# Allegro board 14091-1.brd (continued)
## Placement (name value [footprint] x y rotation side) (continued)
C1744  SC10U6D3V3MX-DL-GP  [C603H36]  124.37 204.22 0 top
C1745  SC2D2U10V3KX-1DLGP-U  [C603H36]  124.24 223.9 180 top
C1753  SCD1U16V2KX-3DLGP  [C402H22]  175.67 105.66 180 top
C1756  SC1KP50V2KX-1DLGP  [C402H22]  164.5 118.36 0 top
C1757  SCD1U16V2KX-3DLGP  [C402H22]  160.43 116.71 90 top
C1760  SCD1U16V2KX-3DLGP  [C402H22]  30.13 23.24 270 bottom
C1764  SCD01U50V2KX-1DLGP  [C402H22]  122.33 12.32 270 bottom
C1769  SCD1U16V2KX-3DLGP  [C402H22]  120.56 7.87 0 bottom
C1770  SC10U10V5KX-2DLGP  [C805H50]  160.18 192.02 270 top
C1771  SC10U10V5KX-2DLGP  [C805H50]  160.18 194.06 270 top
C1773  SC10P50V2JN-4DLGP  [C402H22]  30.77 11.18 270 top
C1774  SC10P50V2JN-4DLGP  [C402H22]  32.67 11.18 90 top
C1780  SC100P50V2JN-3DLGP  [C402H22]  156.5 80.39 90 bottom
C1796  SC1U16V3KX-2DLGP  [C603H36]  80.17 214 90 bottom
C1797  SC1U16V3KX-2DLGP  [C603H36]  80.17 210.57 90 bottom
C1798  SC1U10V2KX-1DLGP  [C402H22]  32.16 7.57 90 bottom
C1799  SC18P50V2JN-1DLGP  [C402H22]  39.15 9.4 90 top
C1800  SC18P50V2JN-1DLGP  [C402H22]  35.72 10.29 270 top
C1801  SC1U25V3KX-1-DLGP  [C603H36]  36.14 13.41 270 bottom
C1802  SC2D2U10V3KX-1DLGP-U  [C603H36]  73.69 29.34 0 top
C1803  SC4D7U6D3V3KX-DLGP  [C603H36]  46.26 15.88 270 top
C1804  SC4D7U6D3V3KX-DLGP  [C603H36]  46.26 14.61 270 top
C1805  SCD1U16V2KX-3DLGP  [C402H22]  30.51 16.38 270 top
C1806  SCD1U16V2KX-3DLGP  [C402H22]  74.71 29.72 0 top
C1807  SCD1U25V3KX-DLGP  [C603H36]  33.31 12.95 180 top
C1808  SCD1U16V2KX-3DLGP  [C402H22]  30.51 15.37 270 top
C1829  SC1U10V2KX-1DLGP  [C402H22]  127.92 4.57 270 top
C1830  SC1U10V2KX-1DLGP  [C402H22]  128.3 9.91 270 top
C1831  SC1U6D3V2KX-DLGP  [C402H22]  128.68 11.3 270 bottom
C1832  SCD1U16V2KX-3DLGP  [C402H22]  126.02 4.57 90 top
C1833  SC10U10V5KX-2DLGP  [C805H50]  122.97 6.86 180 top
C1834  SCD1U16V2KX-3DLGP  [C402H22]  123.1 10.92 270 top
C1835  SC10U10V5KX-2DLGP  [C805H50]  123.73 12.83 270 top
C1836  SC1KP50V2KX-1DLGP  [C402H22]  123.1 10.03 270 top
C1837  SC1KP50V2KX-1DLGP  [C402H22]  123.1 9.14 270 top
C1838  SCD22U10V2KX-2-GP  [C402H22]  88.3 115.32 270 bottom
C1839  SCD22U10V2KX-2-GP  [C402H22]  87.41 112.52 270 bottom
C1840  SCD22U10V2KX-2-GP  [C402H22]  88.3 116.2 270 bottom
C1841  SCD22U10V2KX-2-GP  [C402H22]  92.62 115.7 180 bottom
C1842  SCD22U10V2KX-2-GP  [C402H22]  87.41 113.41 270 bottom
C1843  SCD22U10V2KX-2-GP  [C402H22]  85 113.03 180 bottom
C1844  SCD22U10V2KX-2-GP  [C402H22]  93.51 115.7 180 bottom
C1845  SCD22U10V2KX-2-GP  [C402H22]  84.11 113.03 180 bottom
C1846  SCD1U10V2KX-5DLGP  [C402H22]  92.69 97.97 180 bottom
C1847  SCD082U16V2KX-1-GP  [C402H22]  97.19 96.77 0 top
C1848  SCD68U16V3KX-3-GP  [C603H38]  97.32 99.19 0 top
C1849  SCD082U16V2KX-1-GP  [C402H22]  97.19 94.87 180 top
C1850  SCD082U16V2KX-1-GP  [C402H22]  97.19 92.96 0 top
C1851  SCD1U16V2KX-3DLGP  [C402H22]  48.67 105.79 270 top
C1852  SCD1U16V2KX-3DLGP  [C402H22]  48.67 104.9 270 top
C1853  SCD1U16V2KX-3DLGP  [C402H22]  49.41 88.7 180 top
C1854  SCD1U16V2KX-3DLGP  [C402H22]  47.02 114.05 180 top
C1855  SCD01U50V2KX-1DLGP  [C402H22]  46.77 112.27 90 top
C1856  SCD1U16V2KX-3DLGP  [C402H22]  48.67 103.12 270 top
C1857  SCD1U16V2KX-3DLGP  [C402H22]  48.42 113.67 90 bottom
C1858  SC10U6D3V3MX-DL-GP  [C603H36]  48.17 82.68 90 bottom
C1859  SCD1U16V2KX-3DLGP  [C402H22]  48.42 89.66 90 bottom
C1860  SCD1U16V2KX-3DLGP  [C402H22]  47.4 95.76 90 bottom
C1861  SCD1U16V2KX-3DLGP  [C402H22]  47.79 96.65 270 top
C1864  SCD01U50V2KX-1DLGP  [C402H22]  163.23 91.19 0 top
C1867  SC1U10V2KX-1DLGP  [C402H22]  47.28 91.19 180 bottom
C1868  SCD1U16V2KX-3DLGP  [C402H22]  46.39 91.19 180 bottom
C1869  SCD1U16V2KX-3DLGP  [C402H22]  48.44 94.76 90 bottom
C1925  SC10U10V5KX-2DLGP  [C805H50]  148.37 12.7 90 bottom
C1926  SCD1U16V2KX-3DLGP  [C402H22]  151.42 7.24 270 bottom
C1927  SC10U10V5KX-2DLGP  [C805H50]  150.66 5.08 270 bottom
C1928  SC1KP50V2KX-1DLGP  [C402H22]  151.42 9.02 270 bottom
C1929  SC1KP50V2KX-1DLGP  [C402H22]  151.42 8.13 270 bottom
C2101  SC1U10V2KX-1DLGP  [C402H22]  52.87 139.83 0 top
C2102  SC1U10V2KX-1DLGP  [C402H22]  83.09 157.61 0 bottom
C2103  SC1U10V2KX-1DLGP  [C402H22]  88.43 141.53 270 top
C2104  SC1U10V2KX-1DLGP  [C402H22]  77.5 141.48 90 top
C2105  SC1U10V2KX-1DLGP  [C402H22]  69.88 138.68 270 top
C2106  SC1U10V2KX-1DLGP  [C402H22]  79.54 132.97 90 top
C2107  SC1U10V2KX-1DLGP  [C402H22]  81.06 137.29 180 top
C2108  SC1U10V2KX-1DLGP  [C402H22]  83.35 138.68 270 top
C2109  SC1U10V2KX-1DLGP  [C402H22]  99.35 128.73 0 top
C2110  SCD1U16V2KX-3DLGP  [C402H22]  98.48 128.73 0 top
C2111  SC1U10V2KX-1DLGP  [C402H22]  86.52 157.23 90 bottom
C2112  SCD1U16V2KX-3DLGP  [C402H22]  98.84 147.47 0 top
C2113  SC47U6D3V5MX-1DL-GP  [C805H54]  42.07 138.68 0 top
C2114  SC47U6D3V5MX-1DL-GP  [C805H54]  46.26 138.68 0 top
C2115  SC47U6D3V5MX-1DL-GP  [C805H54]  44.23 138.68 0 top
C2116  SC1U10V2KX-1DLGP  [C402H22]  68.23 148.21 180 top
C2117  SC1U10V2KX-1DLGP  [C402H22]  102.52 148.84 270 top
C2118  SCD1U16V2KX-3DLGP  [C402H22]  102.52 147.96 270 top
C2119  SCD1U16V2KX-3DLGP  [C402H22]  102.52 147.07 270 top
C2120  SC1U10V2KX-1DLGP  [C402H22]  100.87 150.5 0 top
C2121  SCD1U16V2KX-3DLGP  [C402H22]  101.76 150.5 180 top
C3131  SC100P3KV8JN-4-GP  [C1808H87]  65.18 18.16 0 bottom
C3366  SCD1U16V2KX-3DLGP  [C402H22]  141.51 39.93 180 bottom
C3367  SC10U10V5KX-2DLGP  [C805H50]  133.64 33.15 90 bottom
C3452  SCD01U50V2KX-1DLGP  [C402H22]  49.82 17.78 180 top
C3453  SCD1U16V2KX-3DLGP  [C402H22]  38.9 12.57 0 bottom
C3454  SCD1U16V2KX-3DLGP  [C402H22]  35.85 17.53 180 bottom
C3455  SCD1U25V2KX-1-DL-GP  [C402H22]  37.29 20.45 180 bottom
C3456  SCD1U25V2KX-1-DL-GP  [C402H22]  38.01 24.77 180 top
C3457  SCD01U50V2KX-1DLGP  [C402H22]  39.4 25.27 270 top
C3458  SCD01U50V2KX-1DLGP  [C402H22]  39.4 27.3 270 top
C3459  SC10U25V5KX-DL-GP  [C805H58]  45.32 33.43 90 top
C3460  SC10U25V5KX-DL-GP  [C805H58]  45.37 35.69 90 top
C4101  SC1U10V2KX-1DLGP  [C402H22]  103.18 59.56 180 top
C4254  SC10U6D3V3MX-DL-GP  [C603H36]  42.96 109.47 270 bottom
C6701  SCD1U16V2KX-3DLGP  [C402H22]  88.91 64.52 180 top
C6702  SCD1U16V2KX-3DLGP  [C402H22]  88.91 66.45 0 top
C6703  SC10U6D3V3MX-DL-GP  [C603H36]  82.58 65.68 270 top
C6710  SC10U6D3V3MX-DL-GP  [C603H36]  48.42 118.24 270 top
C6711  SCD1U16V2KX-3DLGP  [C402H22]  48.67 104.01 270 top
C6716  SC10U6D3V3MX-DL-GP  [C603H36]  42.96 110.74 270 bottom
C6717  SCD1U16V2KX-3DLGP  [C402H22]  42.96 108.33 90 bottom
C6718  SCD1U16V2KX-3DLGP  [C402H22]  49.44 121.16 180 top
C6724  SCD01U25V2KX-3DLGP  [C402H22]  101 66.93 0 bottom
C6725  SCD1U10V2KX-4GP  [C402H20]  93.89 65.91 270 bottom
C9504  SCD1U16V2KX-3DLGP  [C402H22]  64.55 75.95 180 bottom
C9516  SC4D7U6D3V3KX-DLGP  [C603H36]  58.58 69.22 270 bottom
C9518  SCD1U16V2KX-3DLGP  [C402H22]  56.04 75.82 0 bottom
C9520  SC18P50V2JN-1DLGP  [C402H22]  69.78 52.07 180 top
C9522  SC18P50V2JN-1DLGP  [C402H22]  69.78 50.14 0 top
C9901  SCD1U16V2KX-3DLGP  [C402H22]  19.85 224.66 180 top
C9902  SCD1U16V2KX-3DLGP  [C402H22]  21.24 224.92 0 bottom
C9903  SCD1U16V2KX-3DLGP  [C402H22]  45.37 224.03 180 top
C9904  SCD1U16V2KX-3DLGP  [C402H22]  25.43 224.41 0 bottom
C9905  SCD1U16V2KX-3DLGP  [C402H22]  30.94 224.18 180 top
C11358  SC1U10V2KX-1DLGP  [C402H22]  154.72 64.64 0 top
C11359  SCD1U16V2KX-3DLGP  [C402H22]  153.83 64.64 0 top
C12126  SC47P50V3JN-DLGP  [C603H35]  129.45 56.64 0 bottom
C12131  SC10U10V5KX-2DLGP  [C805H50]  176.82 136.91 180 bottom
C12151  SC2D2U6D3V2MX-DL-GP  [C402H22]  126.04 63.8 180 top
C12152  SC1U10V2KX-1DLGP  [C402H22]  129.45 58.93 180 bottom
C12155  SCD1U16V2KX-3DLGP  [C402H22]  175.42 135.51 180 bottom
C12156  SC1U10V2KX-1DLGP  [C402H22]  170.34 149.99 180 bottom
C12157  SC4D7U6D3V3KX-DLGP  [C603H36]  170.34 136.75 90 bottom
C12158  SCD1U16V2KX-3DLGP  [C402H22]  170.72 137.79 270 bottom
C12159  SC1U10V2KX-1DLGP  [C402H22]  169.58 142.88 270 bottom
C12160  SCD1U16V2KX-3DLGP  [C402H22]  176.94 139.95 90 bottom
C12161  SC1U10V2KX-1DLGP  [C402H22]  174.79 138.94 90 bottom
C12162  SCD1U16V2KX-3DLGP  [C402H22]  173.9 149.73 270 bottom
C12163  SC4D7U6D3V3KX-DLGP  [C603H36]  173.9 150.88 90 bottom
C12169  SC4D7U6D3V3KX-DLGP  [C603H36]  53.5 59.44 270 bottom
C12170  SCD1U16V2KX-3DLGP  [C402H22]  79.66 56.77 90 top
C12171  SCD1U50V3KX-DL-GP  [C603H35]  65.18 64.64 270 bottom
C12172  SCD1U16V2KX-3DLGP  [C402H22]  56.68 66.42 0 bottom
C12174  SC10U10V5KX-2DLGP  [C805H50]  67.47 54.74 270 bottom
C12175  SCD1U16V2KX-3DLGP  [C402H22]  75.6 51.05 270 top
C12176  SCD1U16V2KX-3DLGP  [C402H22]  75.6 50.16 270 top
C12179  SCD1U16V2KX-3DLGP  [C402H22]  72.8 60.58 270 top
C12180  SCD1U16V2KX-3DLGP  [C402H22]  72.8 61.47 270 top
C12181  SCD1U16V2KX-3DLGP  [C402H22]  72.8 62.36 270 top
C12182  SCD1U16V2KX-3DLGP  [C402H22]  72.8 63.25 270 top
C12183  SCD1U16V2KX-3DLGP  [C402H22]  62.39 51.56 90 top
C12184  SCD1U16V2KX-3DLGP  [C402H22]  56.42 51.82 270 top
C12185  SC10U6D3V3MX-DL-GP  [C603H36]  73.19 55.37 90 top
C12186  SCD1U16V2KX-3DLGP  [C402H22]  68.49 57.53 180 bottom
C12187  SCD1U16V2KX-3DLGP  [C402H22]  72.55 54.36 90 top
C12188  SCD1U16V2KX-3DLGP  [C402H22]  67.85 64.14 90 bottom
C12189  SC4D7U6D3V3KX-DLGP  [C603H36]  72.8 55.5 270 bottom
C12190  SC1U25V3KX-1-DLGP  [C603H36]  73.57 75.82 90 top
C12191  SCD1U16V2KX-3DLGP  [C402H22]  65.44 75.95 180 bottom
C12192  SC1U10V2KX-1DLGP  [C402H22]  71.79 77.6 90 top
C12193  SC1U10V2KX-1DLGP  [C402H22]  71.79 78.49 90 top
C12194  SCD1U16V2KX-3DLGP  [C402H22]  56.93 75.82 0 bottom
C12195  SCD1U16V2KX-3DLGP  [C402H22]  57.82 75.82 0 bottom
C12196  SCD1U16V2KX-3DLGP  [C402H22]  55.66 71.12 270 bottom
C12197  SCD1U16V2KX-3DLGP  [C402H22]  54.14 64.39 180 bottom
C12199  SCD1U16V2KX-3DLGP  [C402H22]  119.41 32.64 0 bottom
C12200  SCD1U16V2KX-3DLGP  [C402H22]  137.07 39.62 90 top
C12201  SCD01U50V2KX-1DLGP  [C402H22]  135.42 30.99 270 bottom
C12202  SCD1U16V2KX-3DLGP  [C402H22]  136.81 31.65 0 top
C12203  SCD01U50V2KX-1DLGP  [C402H22]  130.21 40.51 270 top
C12204  SCD1U16V2KX-3DLGP  [C402H22]  129.32 31.6 270 top
C12205  SCD01U50V2KX-1DLGP  [C402H22]  130.21 39.62 270 top
C12206  SCD1U16V2KX-3DLGP  [C402H22]  135.03 41.15 180 top
C12207  SCD01U50V2KX-1DLGP  [C402H22]  135.92 41.15 180 top
C12208  SCD1U16V2KX-3DLGP  [C402H22]  139.35 36.2 270 top
C12209  SCD1U16V2KX-3DLGP  [C402H22]  139.35 37.08 270 top
C12210  SCD1U16V2KX-3DLGP  [C402H22]  139.35 34.42 270 top
C12211  SCD1U16V2KX-3DLGP  [C402H22]  139.35 35.31 270 top
C12212  SCD1U16V2KX-3DLGP  [C402H22]  139.35 32.38 270 top
C12213  SCD1U16V2KX-3DLGP  [C402H22]  139.35 33.27 270 top
C12214  SCD1U16V2KX-3DLGP  [C402H22]  139.35 37.97 270 top
C12215  SCD1U16V2KX-3DLGP  [C402H22]  139.35 38.86 270 top
C12216  SCD1U16V2ZY-2DLGP  [C402H22]  120.05 23.62 90 top
C12217  SCD1U16V2ZY-2DLGP  [C402H22]  127.19 20.07 90 top
C12218  SC33P50V2JN-3DLGP  [C402H22]  124.62 20.19 180 bottom
C12219  SC33P50V2JN-3DLGP  [C402H22]  124.24 19.05 270 top
C12244  SC10U6D3V3MX-DL-GP  [C603H36]  54.9 75.56 0 bottom
C12245  SC10U10V5KX-2DLGP  [C805H50]  56.8 63.63 180 bottom
C12246  SC10U10V5KX-2DLGP  [C805H50]  56.8 59.94 180 bottom
C12249  SCD1U16V2KX-3DLGP  [C402H22]  141.89 64.52 180 bottom
C12250  SCD1U16V2KX-3DLGP  [C402H22]  118.14 48.01 0 top
C12251  SC1U10V2KX-1DLGP  [C402H22]  148.24 47.75 270 top
C12261  SC1U10V2KX-1DLGP  [C402H22]  39.12 128.27 270 top
C12262  SCD68U16V3KX-4-GP  [C603H36]  153.96 41.4 270 top
C12263  SCD027U50V3KX-DL-GP  [C603H36]  166.43 56.69 0 top
C12264  SCD68U16V3KX-4-GP  [C603H36]  160.43 41.4 270 top
C12265  SCD01U50V3KX-4DLGP  [C603H36]  158.66 37.08 180 bottom
C12266  SC1U25V3KX-1-DLGP  [C603H36]  160.69 56.52 0 top
C12331  SC1U10V2KX-1DLGP  [C402H22]  161.07 58.29 90 top
C12332  SC1U10V2KX-1DLGP  [C402H22]  157.64 58.29 270 top
C12333  SC1KP50V2KX-1DLGP  [C402H22]  165.39 51.69 180 top
C12334  SC1000P50V3JN-DLGP  [C603H36]  159.42 35.31 270 top
C12335  SCD1U25V2KX-1-DL-GP  [C402H22]  151.16 119.38 180 top
C12336  SCD22U10V2KX-2-GP  [C402H22]  60.99 150.5 180 top
C12337  SCD22U10V2KX-2-GP  [C402H22]  63.03 143 90 top
C12338  SCD1U16V2KX-3DLGP  [C402H22]  62.39 150.5 180 top
C12339  SCD1U16V2KX-3DLGP  [C402H22]  63.28 150.5 180 top
C12340  SCD22U10V2KX-2-GP  [C402H22]  63.03 148.21 90 top
C12341  SCD22U10V2KX-2-GP  [C402H22]  63.03 145.41 90 top
C12342  SCD1U16V2KX-3DLGP  [C402H22]  69.12 156.46 270 bottom
C12343  SCD1U16V2KX-3DLGP  [C402H22]  69.12 155.57 270 bottom
C12344  SCD22U10V2KX-2-GP  [C402H22]  63.03 147.32 90 top
C12345  SCD22U10V2KX-2-GP  [C402H22]  63.03 146.3 90 top
C12346  SCD1U16V2KX-3DLGP  [C402H22]  67.98 157.61 90 top
C12347  SCD1U16V2KX-3DLGP  [C402H22]  67.98 158.5 90 top
C12348  SCD22U10V2KX-2-GP  [C402H22]  60.1 150.5 180 top
C12349  SCD22U10V2KX-2-GP  [C402H22]  63.03 143.89 90 top
C12350  SC220P50V2KX-3DLGP  [C402H22]  106.36 126.87 270 bottom
C12351  SCD1U16V2KX-3DLGP  [C402H22]  66.45 192.15 270 top
C12352  SC10U6D3V2MX-2-GP  [C402-TO0D2H28]  56.29 140.34 90 top
C12353  SC1U10V2KX-1DLGP  [C402H22]  107.6 151.26 270 bottom
C12354  SC1U10V2KX-1DLGP  [C402H22]  107.6 152.15 270 bottom
C12355  SC12P50V2JN-DL-GP  [C402H22]  64.42 159.38 0 top
C12356  SC12P50V2JN-DL-GP  [C402H22]  64.93 156.77 90 top
C12357  SC3D3P50V2CN-DL-GP  [C402H22]  90.58 132.97 180 top
C12358  SC3D3P50V2CN-DL-GP  [C402H22]  90.58 131.06 0 top
C12361  SC10U10V5KX-2DLGP  [C805H50]  90.2 7.37 270 top
C12362  SCD1U16V2KX-3DLGP  [C402H22]  90.84 18.8 270 top
C12363  SC1KP50V2KX-1DLGP  [C402H22]  90.33 21.34 180 top
C12364  SC10U10V5KX-2DLGP  [C805H50]  90.2 9.4 270 top
C12365  SCD1U16V2KX-3DLGP  [C402H22]  157.26 102.23 0 bottom
C12368  SCD01U50V2KX-1DLGP  [C402H22]  121.7 71.37 180 top
C12369  SCD1U16V2KX-3DLGP  [C402H22]  114.46 58.55 180 top
C12370  SCD1U16V2KX-3DLGP  [C402H22]  127.92 30.1 180 top
C12371  SCD1U16V2KX-3DLGP  [C402H22]  72.8 64.14 270 top
C12372  SCD1U16V2KX-3DLGP  [C402H22]  72.8 66.67 270 top
C12373  SCD1U16V2KX-3DLGP  [C402H22]  72.8 65.02 270 top
C12374  SCD1U16V2KX-3DLGP  [C402H22]  72.8 67.56 270 top
C12375  SCD1U16V2KX-3DLGP  [C402H22]  160.18 59.69 0 top
C12376  SC6D8P50V2CN-DL-GP  [C402H22]  169.07 141.48 0 bottom
C12377  SC100P50V2JN-3DLGP  [C402H22]  73.82 138.81 90 top
C12378  SC33P50V2JN-3DLGP  [C402H22]  168.69 152.02 180 bottom
C12379  SC33P50V2JN-3DLGP  [C402H22]  168.69 153.92 0 bottom
C12380  SC33P50V2JN-3DLGP  [C402H22]  169.58 146.81 270 bottom
C12381  SC33P50V2JN-3DLGP  [C402H22]  169.58 145.92 270 bottom
C12382  SCD1U16V2KX-3DLGP  [C402H22]  47.79 175.13 135 bottom
C12383  SCD1U16V2KX-3DLGP  [C402H22]  79.41 199.26 315 bottom
C12384  SC1U10V2KX-1DLGP  [C402H22]  92.11 51.05 90 top
C12385  SCD1U16V2KX-3DLGP  [C402H22]  145.45 45.72 270 top
C12386  SCD1U16V2KX-3DLGP  [C402H22]  83.22 31.62 180 top
CN3  ACES-CON4-37-GP  [88459-047N]  85.76 125.09 225 bottom
CONVT1  CLX-CON10-10-GP  [CI1410M1HRL-NH]  25 36.65 270 top
CPU1  SKYLAKE-GP  [BGA1356M4224H54]  83 165 270 top
D1  1SS355-4-GP  [SOD323AKH38]  13.88 220.47 180 top
D2  BAS40C-2-GP  [SOT-23-9H44]  144.94 81.41 180 top
D3  RB551V30-GP  [SOD323AKH38]  140.9 81.28 270 top
D4  TVLST2304BD0-GP  [SOT-6H58]  172.37 105.92 270 top
D7  BAT54A-12-GP  [SOT23-2D4-312H44]  85.76 82.93 270 top
D16  P6SMB27A-1-GP  [DO214AAAK-1121H97]  60.36 22.86 180 top
D19  BAV99GP-GP  [SOT23-2D4-312H48]  58.83 36.2 0 bottom
D21  AZ2015-01H-GP  [SOD523AKH28]  162.47 87.63 90 top
D24  TVLST2304BD0-GP  [SOT-6H58]  106.46 32.26 180 top
D32  BX310F-R1-00000-GP  [D4724AKH44]  33.94 34.42 0 bottom
D34  BAT54A-12-GP  [SOT23-2D4-312H44]  104.81 110.36 90 top
D5201  BAT54C-12-GP  [SOT-23-9H44]  120.05 26.16 0 top
D5202  BZX84-C6V8-GP  [SOT-23-9H44]  114.97 26.16 180 top
D5203  SP3010-04UTG-GP  [SLP2510P8-1H22]  106.59 21.59 0 top
D5204  SP3010-04UTG-GP  [SLP2510P8-1H22]  106.71 11.81 180 top
D5205  1SS355-4-GP  [SOD323AKH38]  125.13 30.1 90 top
D5206  1SS355GP-GP  [SOD323AKH40]  167.67 88.65 180 bottom
D5207  AZ5725-01FDR7G-GP  [SOD882-10D6-1H20]  26.83 24 180 bottom
D5212  BAT54C-11-GP  [SOT23-2D4-312H44]  35.09 140.08 180 bottom
DB1  PIN-CON2-S-GP  [210-41-02GB01]  118.52 112.01 270 top
DCIN1  DC-JACK345-GP  [2DC3115-000111F]  53.25 25.53 270 top
DCIN2  ACES-CONN14G-GP  [88314-077N]  55.64 33.67 180 top
DIMM1  DDR3-204P-262-GP-U  [AS0A621-J4R6-7H-U]  135.3 158.9 90 top
DIMM2  DDR3-204P-142-GP-U  [AS0A626-J8R6-7H]  150.5 158.9 90 top
F1  POLYSW-1D5A6V-12-GP  [POLYSW-2114H30]  162.72 186.94 180 top
F2  POLYSW-2A6V-7-GP  [POLYSW-2114H30]  42.58 112.52 270 bottom
F3  POLYSW-1D5A6V-12-GP  [POLYSW-2114H30]  160.18 189.87 90 top
F5  POLYSW-2A6V-7-GP  [POLYSW-2114H30]  6.26 210.82 0 bottom
F7  POLYSW-1D5A6V-12-GP  [POLYSW-2114H30]  117.51 34.92 0 bottom
F14  POLYSW-2A6V-7-GP  [POLYSW-2114H30]  162.59 121.49 90 top
F15  POLYSW-1D5A6V-12-GP  [POLYSW-2114H30]  24.8 6.1 0 bottom
F16  FUSE-3A32V-26-GP  [FUSE-1608H22]  45.63 39.88 270 top
F17  POLYSW-2A6V-7-GP  [POLYSW-2114H30]  93 5.21 270 top
FANC3  FOX-CON4-30-GP  [HF1804H]  14 211 270 top
G1  COPPER-CLOSE-GP-U  [CON2C-U]  145.32 48.01 90 bottom
GPU1  SUN-S3-XT-GP  [BGA631M23H82]  83 100 90 top
H1  HOLE237R158-GP  [HOLE237R158]  94.38 192.31 180 top
H2  HOLE237R158-GP  [HOLE237R158]  62.39 165.12 180 top
H3  HOLE237R158-GP  [HOLE237R158]  94.38 137.93 180 top
H4  HOLE237R158-GP  [HOLE237R158]  69 123.75 180 top
H5  HOLE237R158-GP  [HOLE237R158]  94.39 76.25 180 top
H6  GEN8D5X8R5X4D5-8-F-A-GP  [GEN8D5X8R5X4D5-8-F-A]  165 225 270 top
H7  GEN315R138-8-F-A-1-GP  [GEN315R138-8-F-A-1]  5 160 180 top
H9  GEN8D5X8R5X4D5-8-F-A-GP  [GEN8D5X8R5X4D5-8-F-A]  25 49.15 180 top
H10  GEN315R178-8-F-A-3-GP  [GEN315R178-8-F-A-1]  165 20 180 top
H11  GEN315R138-8-F-A-2-S-GP  [GEN315R138-8-F-A-2-S]  172.5 64.43 180 top
HDD1  SKT-SATA7P-184-GP-U  [15-02070-5A61-A]  12 142 270 top
HDMI1  SKT-HDMI22-12-GP  [SKT-HDMI22-150077]  113.99 37.03 270 top
HDMI2  SKT-HDMI22-12-GP  [SKT-HDMI22-150077]  113.99 14.03 270 top
HDMI3  ARG-CON20-GP  [LVDFH-02004-TP00]  118.69 37.07 270 top
HDMI4  ARG-CON20-GP  [LVDFH-02004-TP00]  118.7 14.07 270 top
HS6  STF256R109H99-GP  [STF256R109H99]  144.25 214 180 top
L1  HCB2012KF-600T30-GP  [L20125H42]  39.4 114.17 0 bottom
L4  FILTER-4P-123-GP  [L125100-4P-1H36]  164.75 116.33 180 top
L5  FILTER-4P-123-GP  [L125100-4P-1H36]  164.75 114.17 180 top
L6  MHC1608S221NBP-GP  [L603H38]  151.16 47.5 180 top
L7  HCB2012KF-601T20-GP  [L20125H42]  153.58 38.99 0 top
L8  HCB2012KF-601T20-GP  [L20125H42]  155.61 38.99 0 top
L10  HCB2012KF-601T20-GP  [L20125H42]  161.83 38.99 0 top
L11  HCB2012KF-601T20-GP  [L20125H42]  159.8 38.99 0 top
L15  BLM15BD102SN1D-GP  [L402H22]  55.66 33.91 90 bottom
L19  HCB1608KF-800T30-GP  [L603H38]  164.93 86.84 180 top
L20  MCB1005S121FBP-GP  [L402H24]  84.49 37.34 180 top
L21  MCB1005S121FBP-GP  [L402H24]  160.69 66.8 90 top
L25  -  [0R0805-PAD]  117.51 38.48 180 bottom
L47  MCB1005S121FBP-GP  [L402H24]  95.28 101.22 90 bottom
L48  MCB1005S121FBP-GP  [L402H24]  95.28 102.49 90 bottom
L49  MCB1005S121FBP-GP  [L402H24]  73.57 82.8 270 top
L50  MCB1005S121FBP-GP  [L402H24]  75.34 81.66 90 top
L51  MCB1005S121FBP-GP  [L402H24]  71.53 82.8 90 top
L52  MHC1608S221NBP-GP  [L603H38]  95.92 95.63 0 bottom
L53  MHC1608S221NBP-GP  [L603H38]  92.62 94.36 90 bottom
L54  MCB1005S121FBP-GP  [L402H24]  156.75 68.91 90 top
L56  FILTER-4P-123-GP  [L125100-4P-1H36]  164.63 97.28 180 top
L57  FILTER-4P-123-GP  [L125100-4P-1H36]  164.63 95.12 180 top
L61  IND-33UH-85-GP  [L8080-6020H158]  38.13 34.54 270 top
L62  MCB1005S121FBP-GP  [L402H24]  83.35 37.34 180 top
L601  COIL-50OHM-GP  [L125100-4P-1H24]  16.54 170.43 180 top
L602  COIL-50OHM-GP  [L125100-4P-1H24]  16.54 173.86 180 top
L603  COIL-50OHM-GP  [L125100-4P-1H24]  17.94 144.02 270 top
L604  COIL-50OHM-GP  [L125100-4P-1H24]  17.81 150.62 270 top
L9502  MHC1608S181NBP-GP  [L603H38]  65.82 51.94 270 bottom
L9503  MHC1608S181NBP-GP  [L603H38]  53.5 73.53 270 bottom
L9504  MHC1608S181NBP-GP  [L603H38]  53.5 60.71 90 bottom
L9505  MHC1608S181NBP-GP  [L603H38]  54.9 66.04 90 bottom
L9523  MHC1608S181NBP-GP  [L603H38]  72.8 54.23 90 bottom
L9524  MHC1608S181NBP-GP  [L603H38]  149.64 45.09 0 top
L9525  MHC1608S181NBP-GP  [L603H38]  113.57 60.96 180 top
L9526  BLM15HG102SN1D-GP  [L402H22]  92.87 50.04 270 top
LED2  LED-O-23-GP  [LED1608AKH30]  142.53 39.37 0 top
LOUT1  AUDIO-JK419-GP  [JAC331-0140A8B-9H]  76.93 37.66 90 top
LPC1  FOX-CONN14A-S1-GP  [HL5507F]  111.03 53.61 0 top
LVDS1  ACES-CON30-21-GP  [50524-0300N-001]  36.8 95 270 top
MEJ1  JOWLE-CON2-5-GP  [A2541WV0-1EX2PA-6T]  109.13 112.01 90 top
MEM1  H5TQ1G63DFR-11C-1-GP  [BGA96D075130H48]  55.61 111.68 0 top
MEM2  H5TQ1G63DFR-11C-1-GP  [BGA96D075130H48]  55.61 91.62 180 top
MEM3  H5TQ1G63DFR-11C-1-GP  [BGA96D075130H48]  55.61 111.68 180 bottom
MEM4  H5TQ1G63DFR-11C-1-GP  [BGA96D075130H48]  55.61 91.62 0 bottom
MEMCD1  SKT-SDCARD-52-GP  [156-5101902601]  174.65 144.79 90 top
NGFF1  SKT-MINI67P-3-GP-U1  [2199230-7]  116 214 270 top
NOREF  -  []  -10 0 0 top
NOREF#2  *  [unnamed#2]  65.44 141.35 0 top
NOREF#3  -  []  -584.82 -221.92 0 top
NOREF#4  *  [unnamed#2]  5.05 6.01 0 top
NOREF#5  -  []  -10 0 0 top
NOREF#6  -  [unnamed#2]  11.57 4.95 0 top
NOREF#7  -  [unnamed#2]  178.22 223.03 0 top
NOREF#8  -  []  134.4 207.39 0 top
NOREF#9  *  [unnamed#2]  171.63 8.45 0 top
NOREF#10  *  [unnamed#2]  147.23 29.84 0 top
NOREF#11  *  [unnamed#2]  70.39 115.95 0 top
NOREF#12  -  []  112.94 169.67 0 top
NOREF#13  -  []  105.82 193.04 0 top
NOREF#14  *  [unnamed#2]  103.41 81.53 0 top
NOREF#15  -  []  0 113.25 0 top
NOREF#16  *  [unnamed#2]  130.46 67.82 0 top
NOREF#17  -  [unnamed#2]  3.34 226.69 0 top
NOREF#18  -  [unnamed#2]  171.63 4.95 0 top
NOREF#19  -  [unnamed#2]  9.56 12.19 0 top
NOREF#20  *  [unnamed#2]  167.42 207.9 0 top
NOREF#21  *  [unnamed#2]  106.54 198.78 0 top
NOREF#22  *  [unnamed#2]  145.7 39.24 0 top
NOREF#23  -  []  -64.42 3.3 0 top
NOREF#24  -  [unnamed#2]  166.53 216.03 0 top
NOREF#25  -  []  154.08 220.98 0 top
NOREF#26  *  [unnamed#2]  178.33 217.98 0 top
NOREF#27  *  [unnamed#2]  8.8 218.82 0 top
NOREF#28  *  [unnamed#2]  156.88 224.03 180 bottom
NOREF#29  *  [unnamed#2]  171.63 8.45 180 bottom
NOREF#30  *  [unnamed#2]  5.05 6.01 180 bottom
NOREF#31  *  [unnamed#2]  178.33 217.98 180 bottom
NOREF#32  -  []  178.45 28.4 90 bottom
NOREF#33  -  []  121.7 202.44 90 bottom
NOREF#34  *  [unnamed#2]  6 224.16 180 bottom
NOREF#35  *  [unnamed#2]  155.1 29.97 180 bottom
ODD1  SKT-SATA7P-184-GP-U  [15-02070-5A61-A]  8.4 177 270 top
OSC2  OSC-48MHZ-16GP  [SMD-OSC8H52]  118.02 60.33 0 top
P5479  0R2J-2-GP  [R402H16]  42.96 15.75 90 top
P5480  0R2J-2-GP  [R402H16]  42.96 16.76 90 top
P5481  0R2J-2-GP  [R402H16]  42.96 18.16 90 top
P5482  0R2J-2-GP  [R402H16]  42.96 19.18 90 top
PC1  SC1U10V2KX-1DLGP  [C402H22]  146.46 204.09 90 bottom
PC4  SC22P50V2JN-4DLGP  [C402H22]  125.03 107.14 180 top
PC5  SCD22U25V3KX-DL-GP  [C603H36]  126.07 106.55 0 top
PC6  SC150P50V2JN-3DLGP  [C402H22]  129.7 107.57 270 top
PC7  SC1KP50V2KX-1DLGP  [C402H22]  131.61 106.05 270 top
PC8  SC33P50V2JN-3DLGP  [C402H22]  130.21 106.17 0 top
PC9  SCD01U50V2KX-1DLGP  [C402H22]  130.34 102.74 180 bottom
PC11  SC680P50V2KX-2DLGP  [C402H22]  127.67 107.57 90 top
PC12  SCD1U50V3KX-DL-GP  [C603H35]  136.35 102.87 90 top
PC13  SC330P50V2KX-3-DL-GP  [C402H22]  125.26 103.12 0 top
PC14  SCD01U50V2KX-1DLGP  [C402H22]  123.73 101.73 90 top
PC15  SCD033U25V2KX-1-GP  [C402H22]  120.68 100.33 180 top
PC16  SCD22U25V3KX-DL-GP  [C603H36]  121.83 99.95 180 top
PC17  SC1U16V3KX-4DLGP  [C603H36]  131.61 94.13 90 top
PC18  SC1U16V3KX-4DLGP  [C603H36]  131.61 95.33 90 top
PC19  SCD22U25V3KX-DL-GP  [C603H36]  128.18 93.98 0 top
PC20  SCD1U50V3KX-DL-GP  [C603H35]  120.56 101.98 270 top
PC24  SC10U25V6KX-4DL-GP  [C1206H71]  137.19 82.42 0 bottom
PC58  SC1U16V3KX-4DLGP  [C603H36]  124.24 97.79 0 top
PC59  SCD1U16V3KX-3DLGP  [C603H36]  125.64 93.98 180 top
PC60  SCD22U25V3KX-DL-GP  [C603H36]  122.97 95.76 180 top
PC61  SC10U25V6KX-4DL-GP  [C1206H71]  134.91 82.42 0 bottom
PC126  SC22P50V2JN-4DLGP  [C402H22]  157.64 198.75 90 bottom
PC140  SC1U10V2KX-1DLGP  [C402H22]  39.66 5.97 180 bottom
PC701  SC22U6D3V3MX-1-DL-GP  [C603H40]  106.84 180.72 90 bottom
PC702  SC22U6D3V3MX-1-DL-GP  [C603H40]  94.65 157.99 270 bottom
PC703  SC22U6D3V3MX-1-DL-GP  [C603H40]  96.68 175.9 0 bottom
PC1025  SC10U6D3V2MX-2-GP  [C402-TO0D2H28]  58.71 175.64 180 top
PC1026  SC10U6D3V2MX-2-GP  [C402-TO0D2H28]  57.69 175.64 180 top
PC1027  SC10U6D3V2MX-2-GP  [C402-TO0D2H28]  69.81 174.62 0 bottom
PC1028  SC10U6D3V2MX-2-GP  [C402-TO0D2H28]  70.82 174.62 0 bottom
PC1029  SC10U6D3V2MX-2-GP  [C402-TO0D2H28]  87.79 165.94 270 bottom
PC1030  SC10U6D3V2MX-2-GP  [C402-TO0D2H28]  87.79 167 270 bottom
PC1031  SC10U6D3V2MX-2-GP  [C402-TO0D2H28]  59.47 175.64 0 bottom
PC1032  SC10U6D3V2MX-2-GP  [C402-TO0D2H28]  59.72 175.64 180 top
PC1033  SC22U6D3V3MX-1-DL-GP  [C603H40]  78.47 163.86 180 bottom
PC1034  SC10U6D3V2MX-2-GP  [C402-TO0D2H28]  56.68 182.25 90 top
PC1035  SC10U6D3V2MX-2-GP  [C402-TO0D2H28]  58.45 175.64 0 bottom
PC1036  SC22U6D3V3MX-1-DL-GP  [C603H40]  79.64 163.86 180 bottom
PC1037  SC22U6D3V3MX-1-DL-GP  [C603H40]  60.13 180.09 0 bottom
PC1038  SC10U6D3V2MX-2-GP  [C402-TO0D2H28]  68.79 174.62 0 bottom
PC1076  SC10U6D3V2MX-2-GP  [C402-TO0D2H28]  71.84 174.62 0 bottom
PC1126  SC10U6D3V2MX-2-GP  [C402-TO0D2H28]  82.46 190.63 90 top
PC1127  SC10U6D3V2MX-2-GP  [C402-TO0D2H28]  77.25 170.81 180 bottom
PC1128  SC10U6D3V2MX-2-GP  [C402-TO0D2H28]  76.23 170.81 180 bottom
PC1129  SC10U6D3V2MX-2-GP  [C402-TO0D2H28]  76.36 175.77 180 bottom
PC1130  SC10U6D3V2MX-2-GP  [C402-TO0D2H28]  82.46 191.64 90 top
PC1132  SC10U6D3V2MX-2-GP  [C402-TO0D2H28]  82.46 194.69 90 top
PC1133  SC10U6D3V2MX-2-GP  [C402-TO0D2H28]  82.46 192.66 90 top
PC1134  SC10U6D3V2MX-2-GP  [C402-TO0D2H28]  82.46 193.68 90 top
PC1135  SC10U6D3V2MX-2-GP  [C402-TO0D2H28]  82.46 188.59 90 top
PC1139  SC10U6D3V2MX-2-GP  [C402-TO0D2H28]  82.46 189.61 90 top
PC1155  SC10U6D3V2MX-2-GP  [C402-TO0D2H28]  53.88 169.16 180 top
PC1156  SC10U6D3V2MX-2-GP  [C402-TO0D2H28]  54.9 169.16 180 top
PC1157  SC10U6D3V2MX-2-GP  [C402-TO0D2H28]  56.93 169.16 180 top
PC1158  SC10U6D3V2MX-2-GP  [C402-TO0D2H28]  53.7 162.94 0 top
PC1159  SC10U6D3V2MX-2-GP  [C402-TO0D2H28]  57.95 169.16 0 bottom
PC1160  SC10U6D3V2MX-2-GP  [C402-TO0D2H28]  54.77 162.94 180 bottom
PC1183  SC10U6D3V2MX-2-GP  [C402-TO0D2H28]  46.52 162.43 0 top
PC1188  SC10U6D3V2MX-2-GP  [C402-TO0D2H28]  55.91 169.16 180 top
PC1189  SC10U6D3V2MX-2-GP  [C402-TO0D2H28]  57.95 169.16 180 top
PC1190  SC10U6D3V2MX-2-GP  [C402-TO0D2H28]  67.85 163.58 0 bottom
PC1191  SC10U6D3V2MX-2-GP  [C402-TO0D2H28]  55.91 169.16 0 bottom
PC1192  SC10U6D3V2MX-2-GP  [C402-TO0D2H28]  56.93 169.16 0 bottom
PC1193  SC10U6D3V2MX-2-GP  [C402-TO0D2H28]  80.68 161.16 0 bottom
PC1198  SC10U6D3V2MX-2-GP  [C402-TO0D2H28]  40.04 135.51 0 top
PC1199  SC10U6D3V2MX-2-GP  [C402-TO0D2H28]  39.02 135.51 0 top
PC4301  SC10P50V2JN-4DLGP  [C402H22]  32.67 65.28 180 bottom
PC4302  SCD1U50V3KX-DL-GP  [C603H35]  36.48 72.9 180 top
PC4303  SC2200P50V2KX-2DLGP  [C402H22]  37.5 72.77 180 top
PC4304  SC470P50V2KX-3DLGP  [C402H22]  32.67 63.37 0 bottom
PC4305  SC10P50V2JN-4DLGP  [C402H22]  32.67 67.18 0 bottom
PC4401  SCD01U50V2KX-1DLGP  [C402H22]  44.48 43.43 180 top
PC4402  SC10U25V5KX-DL-GP  [C805H58]  36.41 66.9 0 top
PC4403  SC1KP50V2KX-1DLGP  [C402H22]  39.78 73.53 90 bottom
PC4404  SCD1U50V3KX-DL-GP  [C603H35]  34.83 67.34 0 top
PC4405  SCD1U50V3KX-DL-GP  [C603H35]  35.34 45.34 180 bottom
PC4406  SC10U25V5KX-DL-GP  [C805H58]  40.93 50.67 90 bottom
PC4407  SC10U25V5KX-DL-GP  [C805H58]  40.93 50.67 270 top
PC4408  SCD1U50V3KX-DL-GP  [C603H35]  47.05 46.74 270 top
PC4409  SC470P50V2KX-3DLGP  [C402H22]  38.01 47.24 270 top
PC4410  SCD1U50V3KX-DL-GP  [C603H35]  47.05 45.57 270 top
PC4411  SCD1U25V2KX-1-DL-GP  [C402H22]  36.36 44.2 180 bottom
PC4412  SC220P50V2KX-3DLGP  [C402H22]  43.59 43.43 180 top
PC4413  SCD1U50V3KX-DL-GP  [C603H35]  46.13 46.61 0 bottom
PC4414  SC10U25V5KX-DL-GP  [C805H58]  32.8 74.93 180 top
PC4415  SCD1U50V3KX-DL-GP  [C603H35]  43.21 49.12 270 bottom
PC4416  SC1U10V2KX-1DLGP  [C402H22]  38.01 47.37 270 bottom
PC4417  SCD1U25V2KX-1-DL-GP  [C402H22]  41.05 52.2 90 bottom
PC4418  SC1U25V5KX-3-GP  [C805H58]  44.74 46.99 0 top
PC4419  SC10U25V5KX-DL-GP  [C805H58]  34.83 72.64 180 top
PC4426  SC1U25V3KX-1-GP  [C603H36]  25.81 69.47 0 bottom
PC4501  SCD1U16V2KX-3DLGP  [C402H22]  137.32 12.7 0 top
PC4502  SC22P50V2JN-4DLGP  [C402H22]  155.74 24.05 0 top
PC4503  SC1U10V2KX-1DLGP  [C402H22]  156.37 18.41 90 top
PC4504  SC1500P50V3KX-DLGP  [C603H36]  138.41 19.08 180 top
PC4505  SC4D7U6D3V3KX-DLGP  [C603H36]  148.37 20.32 0 top
PC4506  SCD1U50V3KX-DL-GP  [C603H35]  148.55 26.54 270 top
PC4507  SC10U25V5KX-DL-GP  [C805H58]  148.24 24.97 270 top
PC4508  SCD1U50V3KX-DL-GP  [C603H35]  150.53 27.3 0 top
PC4509  SCD1U50V3KX-DL-GP  [C603H35]  132.62 23.37 270 bottom
PC4510  SC10U25V5KX-DL-GP  [C805H58]  143.29 25.02 90 bottom
PC4511  SCD1U16V2KX-3DLGP  [C402H22]  146.97 12.7 0 top
PC4512  SC18P50V2JN-1DLGP  [C402H22]  155.02 23.62 0 bottom
PC4513  SC18P50V2JN-1DLGP  [C402H22]  155.02 21.72 180 bottom
PC4514  SCD1U50V3KX-DL-GP  [C603H35]  151.04 17.27 0 top
PC4515  SC10U25V5KX-DL-GP  [C805H58]  132.62 25.02 270 bottom
PC4516  SC4D7U6D3V3KX-DLGP  [C603H36]  149.51 15.62 0 top
PC4517  SC10U25V5KX-DL-GP  [C805H58]  143.29 27.05 90 bottom
PC4518  SCD1U50V3KX-DL-GP  [C603H35]  143.29 23.37 90 bottom
PC4528  SC22P50V2JN-4DLGP  [C402H22]  155.74 19.81 180 top
PC4601  SCD22U25V3KX-DL-GP  [C603H36]  32.42 206.38 90 bottom
PC4602  SC470P50V2KX-3DLGP  [C402H22]  23.15 199.75 270 top
PC4603  SC1500P50V2KX-2-DL-GP  [C402H22]  22 208.03 0 top
PC4604  SCD01U50V2KX-1DLGP  [C402H22]  24.54 204.34 0 top
PC4605  SCD015U25V2KX-DLGP  [C402H22]  21.7 203.63 0 top
PC4606  SC15P50V2JN-DL-GP  [C402H22]  23.15 203.55 270 top
PC4607  SCD015U25V3KX-DL-GP  [C603H36]  19.34 200.66 270 bottom
PC4608  SCD015U25V2KX-DLGP  [C402H22]  27.97 192.41 0 top
PC4609  SC1KP50V2KX-1DLGP  [C402H22]  20.56 207.52 270 top
PC4611  SC470P50V2KX-3DLGP  [C402H22]  26.7 194.36 0 bottom
PC4612  SCD1U25V2KX-1-DL-GP  [C402H22]  26.45 208.79 90 bottom
PC4613  SCD033U25V2KX-1-GP  [C402H22]  28.86 192.41 0 top
PC4614  SC220P50V2KX-3DLGP  [C402H22]  18.58 209.63 180 bottom
PC4615  SC47P50V2JN-5DLGP  [C402H22]  21.24 207.77 90 bottom
PC4616  SC2D2U10V3KX-1DLGP-U  [C603H36]  32.67 201.17 90 top
PC4617  SCD22U25V3KX-DL-GP  [C603H36]  32.39 198.96 270 bottom
PC4618  SC15P50V2JN-DL-GP  [C402H22]  29.62 195.2 180 bottom
PC4619  SCD01U25V2KX-3DLGP  [C402H22]  30.51 195.2 180 bottom
PC4620  SC1KP50V2KX-1DLGP  [C402H22]  20.86 192.15 270 top
PC4621  SC470P50V2KX-3DLGP  [C402H22]  33.31 192.91 270 top
PC4622  SCD1U25V2KX-1-DL-GP  [C402H22]  23.66 190.5 0 top
PC4623  SC1KP50V2KX-1DLGP  [C402H22]  31.4 192.91 90 top
PC4624  SC2200P50V2KX-2DLGP  [C402H22]  31.38 196.06 0 top
PC4625  SC1KP50V2KX-1DLGP  [C402H22]  27.59 195.2 180 bottom
PC4626  SC6800P25V2KX-1DLGP  [C402H22]  19.72 199.64 90 bottom
PC4627  SC1U50V5KX-DL-GP  [C805H54]  27.72 203.71 0 top
PC4628  SC1KP50V2KX-1DLGP  [C402H22]  23.12 201.64 90 top
PC4629  SCD01U50V2KX-1DLGP  [C402H22]  26.32 204.34 0 top
PC4630  SC100P50V2JN-3DLGP  [C402H22]  23.3 210.06 270 bottom
PC4631  SC2200P50V2KX-2DLGP  [C402H22]  21.88 209.17 180 bottom
PC4632  SCD1U25V2KX-1-DL-GP  [C402H22]  28.48 208.79 90 bottom
PC4633  SC470P50V2KX-3DLGP  [C402H22]  20.1 193.8 270 top
PC4634  SCD22U25V3KX-DL-GP  [C603H36]  32.77 201.42 90 bottom
PC4635  SCD1U25V2KX-1-DL-GP  [C402H22]  25.43 204.34 0 top
PC4636  SCD1U25V2KX-1-DL-GP  [C402H22]  31.53 195.2 180 bottom
PC4637  SC470P50V2KX-3DLGP  [C402H22]  19.34 204.6 270 bottom
PC4638  SC1KP50V2KX-1DLGP  [C402H22]  21.62 195.2 180 top
PC4639  SC470P50V2KX-3DLGP  [C402H22]  23.3 209.17 270 bottom
PC4702  SC1KP50V2KX-1DLGP  [C402H22]  25.69 185.55 0 top
PC4725  SC10U25V5KX-DL-GP  [C805H58]  21.88 178.18 0 bottom
PC4726  SC10U25V5KX-DL-GP  [C805H58]  25.94 178.18 0 bottom
PC4727  SC10U25V5KX-DL-GP  [C805H58]  23.91 178.18 0 bottom
PC4728  SC10U25V5KX-DL-GP  [C805H58]  19.85 178.18 0 bottom
PC4801  SC10U25V5KX-DL-GP  [C805H58]  38.26 211.96 180 bottom
PC4802  SC10U25V5KX-DL-GP  [C805H58]  40.29 211.96 180 bottom
PC4803  SC10U25V5KX-DL-GP  [C805H58]  41.05 219.33 0 bottom
PC4804  SC10U25V5KX-DL-GP  [C805H58]  39.02 219.33 0 bottom
PC4805  SC10U25V5KX-DL-GP  [C805H58]  35.09 198.12 0 bottom
PC4806  SC10U25V5KX-DL-GP  [C805H58]  40.88 198.12 0 bottom
PC4807  SC10U25V5KX-DL-GP  [C805H58]  37.02 198.12 0 bottom
PC4808  SC10U25V5KX-DL-GP  [C805H58]  38.95 198.12 0 bottom
PC4809  SC1KP50V2KX-1DLGP  [C402H22]  41.94 212.98 180 bottom
PC4810  SC1KP50V2KX-1DLGP  [C402H22]  42.83 198.25 90 bottom
PC5002  SC10U25V5KX-DL-GP  [C805H58]  30.51 165.48 0 top
PC5003  SC10U25V5KX-DL-GP  [C805H58]  30.51 165.48 180 bottom
PC5004  SC2D2U10V3KX-1DLGP-U  [C603H36]  23.27 162.05 180 top
PC5020  SCD22U25V3KX-DL-GP  [C603H36]  27.59 164.85 90 top
PC5101  SC10U25V5KX-DL-GP  [C805H58]  85 224.03 180 top
PC5102  SCD033U25V3KX-DL-GP  [C603H36]  84.36 205.87 180 bottom
PC5103  SC1U10V2KX-1DLGP  [C402H22]  84.49 216.41 0 bottom
PC5104  SC10U10V5KX-2DLGP  [C805H50]  88.04 205.74 180 bottom
PC5105  SCD1U50V3KX-DL-GP  [C603H35]  88.93 224.41 0 bottom
PC5106  SC10U25V5KX-DL-GP  [C805H58]  89.06 224.03 180 top
PC5107  SC10U25V5KX-DL-GP  [C805H58]  87.03 224.03 180 top
PC5109  SC1U16V3KX-4DLGP  [C603H36]  90.46 204.6 270 top
PC5110  SC1500P50V3KX-DLGP  [C603H36]  96.93 224.41 0 bottom
PC5111  SC1KP50V2KX-1DLGP  [C402H22]  87.92 216.79 180 bottom
PC5112  SC18P50V2JN-1DLGP  [C402H22]  79.15 208.91 0 bottom
PC5113  SC10U10V5KX-2DLGP  [C805H50]  86.01 205.74 180 bottom
PC5114  SCD1U50V3KX-DL-GP  [C603H35]  91.35 213.49 0 bottom
PC5115  SC1U10V2KX-1DLGP  [C402H22]  82.96 215.9 270 bottom
PC5199  SC10U10V5KX-2DLGP  [C805H50]  90.33 210.31 90 top
PC5202  SC1U10V2KX-1DLGP  [C402H22]  25.31 152.02 90 bottom
PC5203  SC18P50V2JN-1DLGP  [C402H22]  22.26 154.94 270 top
PC5204  SC10U25V5KX-DL-GP  [C805H58]  28.48 150.24 0 bottom
PC5205  SC1KP50V2KX-1DLGP  [C402H22]  32.65 149.17 90 bottom
PC5206  SCD1U50V3KX-DL-GP  [C603H35]  27.44 150.16 180 top
PC5207  SC1KP50V2KX-1DLGP  [C402H22]  22.82 150.37 180 top
PC5209  SCD1U16V2KX-3DLGP  [C402H22]  56.68 141.86 0 top
PC5223  SC10U6D3V3MX-DL-GP  [C603H36]  90.46 128.78 0 top
PC5224  SC1U25V3KX-1-DLGP  [C603H36]  83.73 126.49 0 top
PC5225  SC10U6D3V3MX-DL-GP  [C603H36]  97.44 127.13 270 top
PC5226  SC100P50V2JN-3DLGP  [C402H22]  96.17 124.21 0 top
PC5227  SC10U6D3V3MX-DL-GP  [C603H36]  97.44 125.86 90 top
PC5228  SC22P50V2JN-4DLGP  [C402H22]  88.55 119.89 0 top
PC5229  SCD1U16V2KX-3DLGP  [C402H22]  84.74 126.11 180 top
PC5299  SC10U25V5KX-DL-GP  [C805H58]  30.51 150.24 0 bottom
PC5301  SCD22U25V3KX-DL-GP  [C603H36]  115.1 70.61 180 top
PC5302  SC1500P50V3KX-DLGP  [C603H36]  108.49 70.36 270 top
PC5303  SC22U6D3V3MX-1-DL-GP  [C603H40]  106.33 72.64 0 top
PC5304  SC22P50V2JN-4DLGP  [C402H22]  120.56 70.36 180 top
PC5305  SC22U6D3V3MX-1-DL-GP  [C603H40]  105.06 72.64 0 top
PC5306  SC22U6D3V3MX-1-DL-GP  [C603H40]  106.21 77.98 180 top
PC5307  SC22U6D3V3MX-1-DL-GP  [C603H40]  104.94 77.98 180 top
PC5308  SC1U10V2KX-1DLGP  [C402H22]  117.51 70.36 0 top
PC5309  SC10U25V5KX-DL-GP  [C805H58]  123.1 72.26 0 top
PC5310  SCD1U25V2KX-1-DL-GP  [C402H22]  107.35 72.77 0 top
PC5311  SC10U25V5KX-DL-GP  [C805H58]  123.09 75.89 180 top
PC5312  SC1500P50V3KX-DLGP  [C603H36]  119.79 79.25 0 top
PC8401  SC22P50V2JN-4DLGP  [C402H22]  113.57 100.84 180 top
PC8402  SC680P50V2KX-2DLGP  [C402H22]  111.54 100.84 180 top
PC8403  SC22U6D3V5MX-2DLGP  [C805H54]  106.46 107.44 90 top
PC8404  SCD1U25V2KX-1-DL-GP  [C402H22]  105.44 100.84 0 top
PC8405  SC22U6D3V5MX-2DLGP  [C805H54]  104.05 101.22 0 top
PC8406  SC10U6D3V3MX-DL-GP  [C603H36]  112.05 108.33 270 top
PC8407  SC10U6D3V3MX-DL-GP  [C603H36]  112.05 107.06 270 top
PC8408  SC1U10V2KX-1DLGP  [C402H22]  114.97 103.38 90 top
PC8409  SCD1U25V2KX-1-DL-GP  [C402H22]  110.14 100.76 270 top
PC8501  SC10U10V5KX-2DLGP  [C805H50]  101.38 72.39 90 top
PC8502  SC10U10V5KX-2DLGP  [C805H50]  88.43 71.25 180 top
PC12172  SCD1U16V2KX-3DLGP  [C402H22]  55.41 60.2 180 bottom
PC12175  SC1500P50V3KX-DLGP  [C603H36]  130.03 84.02 90 top
PC12176  SC330P50V2KX-3-DL-GP  [C402H22]  127.8 102.23 270 bottom
PC12177  SC10U25V6KX-4DL-GP  [C1206H71]  137.45 82.42 180 top
PC12178  SC10U25V6KX-4DL-GP  [C1206H71]  135.16 82.42 180 top
PC12179  SCD01U50V2KX-1DLGP  [C402H22]  84.49 108.97 180 bottom
PC12180  SC1KP50V2KX-1DLGP  [C402H22]  127.8 101.35 90 bottom
PC12181  SCD1U50V3KX-DL-GP  [C603H35]  133.23 82.04 0 bottom
PC12184  SC1500P50V3KX-DLGP  [C603H36]  137.96 19.18 0 bottom
PC12185  SCD1U16V2KX-3DLGP  [C402H22]  105.82 68.83 180 top
PC12186  SC10U10V5KX-2DLGP  [C805H50]  101.38 70.36 90 top
PC12187  SCD1U16V2KX-3DLGP  [C402H22]  104.81 68.83 180 top
PC12188  SC10U10V5KX-2DLGP  [C805H50]  86.39 71.25 180 top
PC12189  SC27P50V2JN-2DLGP  [C402H22]  85.89 76.33 0 top
PC12190  SC1U25V3KX-1-DLGP  [C603H36]  100.36 66.55 0 top
PC12191  SCD1U16V2KX-3DLGP  [C402H22]  89.82 70.99 180 top
PC12370  SC22U6D3V5MX-2DLGP  [C805H54]  69.38 164.47 180 bottom
PC12371  SC22U6D3V5MX-2DLGP  [C805H54]  47.79 187.58 180 top
PC12372  SC22U6D3V5MX-2DLGP  [C805H54]  48.93 172.85 180 bottom
PC12373  SC22U6D3V5MX-2DLGP  [C805H54]  52.79 172.85 180 bottom
PC12374  SC22U6D3V5MX-2DLGP  [C805H54]  50.86 172.85 180 bottom
PC12375  SC22U6D3V5MX-2DLGP  [C805H54]  48.93 172.85 0 top
PC12376  SC22U6D3V5MX-2DLGP  [C805H54]  50.96 172.85 0 top
PC12377  SC22U6D3V5MX-2DLGP  [C805H54]  52.99 172.85 0 top
PC12378  SC22U6D3V5MX-2DLGP  [C805H54]  57.06 172.85 0 top
PC12379  SC22U6D3V3MX-1-DL-GP  [C603H40]  58.2 172.06 180 bottom
PC12380  SC22U6D3V3MX-1-DL-GP  [C603H40]  83.14 163.86 180 bottom
PC12381  SC22U6D3V3MX-1-DL-GP  [C603H40]  84.31 163.86 180 bottom
PC12382  SC22U6D3V3MX-1-DL-GP  [C603H40]  85.66 164.62 180 bottom
PC12383  SC22U6D3V5MX-2DLGP  [C805H54]  56.65 172.82 180 bottom
PC12384  SC22U6D3V5MX-2DLGP  [C805H54]  47.66 187.58 0 bottom
PC12385  SC22U6D3V5MX-2DLGP  [C805H54]  45.63 187.58 0 bottom
PC12386  SC22U6D3V5MX-2DLGP  [C805H54]  54.72 172.82 180 bottom
PC12387  SC22U6D3V5MX-2DLGP  [C805H54]  55.02 172.85 0 top
PC12388  SC22U6D3V5MX-2DLGP  [C805H54]  61.12 172.85 0 top
PC12389  SC22U6D3V5MX-2DLGP  [C805H54]  57.82 179.96 180 top
PC12390  SC22U6D3V5MX-2DLGP  [C805H54]  58.58 180.09 0 bottom
PC12391  SC22U6D3V5MX-2DLGP  [C805H54]  59.85 179.96 180 top
PC12392  SC22U6D3V5MX-2DLGP  [C805H54]  59.09 172.85 0 top
PC12393  SC22U6D3V5MX-2DLGP  [C805H54]  61.88 179.96 180 top
PC12394  SC22U6D3V5MX-2DLGP  [C805H54]  71.03 202.82 0 top
PC12395  SC22U6D3V5MX-2DLGP  [C805H54]  72.25 197.23 180 top
PC12396  SC22U6D3V5MX-2DLGP  [C805H54]  60.61 216.03 0 bottom
PC12397  SC22U6D3V5MX-2DLGP  [C805H54]  65.44 204.98 270 bottom
PC12398  SC22U6D3V5MX-2DLGP  [C805H54]  65.44 202.95 270 bottom
PC12399  SC22U6D3V5MX-2DLGP  [C805H54]  81.82 177.42 270 bottom
PC12400  SC22U6D3V5MX-2DLGP  [C805H54]  82.84 170.56 180 bottom
PC12401  SC22U6D3V5MX-2DLGP  [C805H54]  59.85 184.53 0 top
PC12402  SC22U6D3V5MX-2DLGP  [C805H54]  60.36 184.53 180 bottom
PC12403  SC22U6D3V5MX-2DLGP  [C805H54]  64.93 202.82 0 top
PC12404  SC22U6D3V5MX-2DLGP  [C805H54]  66.96 202.82 0 top
PC12405  SC22U6D3V5MX-2DLGP  [C805H54]  68.99 202.82 0 top
PC12406  SC22U6D3V5MX-2DLGP  [C805H54]  72.68 200.03 270 top
PC12407  SC22U6D3V5MX-2DLGP  [C805H54]  66.28 211.07 180 top
PC12408  SC22U6D3V5MX-2DLGP  [C805H54]  64.35 211.07 180 top
PC12409  SC22U6D3V5MX-2DLGP  [C805H54]  65.44 209.04 270 bottom
PC12410  SC22U6D3V5MX-2DLGP  [C805H54]  65.44 211.07 270 bottom
PC12411  SC22U6D3V5MX-2DLGP  [C805H54]  65.44 213.11 270 bottom
PC12412  SC22U6D3V5MX-2DLGP  [C805H54]  72.8 177.42 90 bottom
PC12413  SC22U6D3V5MX-2DLGP  [C805H54]  85.12 172.97 0 bottom
PC12414  SC22U6D3V5MX-2DLGP  [C805H54]  86.01 183.64 270 bottom
PC12415  SC22U6D3V5MX-2DLGP  [C805H54]  79.41 194.69 315 bottom
PC12416  SC22U6D3V5MX-2DLGP  [C805H54]  57.82 184.53 0 top
PC12417  SC22U6D3V5MX-2DLGP  [C805H54]  81.82 175.39 270 bottom
PC12418  SC22U6D3V5MX-2DLGP  [C805H54]  75.32 190.5 0 top
PC12419  SC22U6D3V5MX-2DLGP  [C805H54]  80.81 170.56 180 bottom
PC12420  SC22U6D3V5MX-2DLGP  [C805H54]  78.77 170.56 180 bottom
PC12421  SC22U6D3V5MX-2DLGP  [C805H54]  81.82 173.35 270 bottom
PC12422  SC22U6D3V5MX-2DLGP  [C805H54]  65.44 207.01 270 bottom
PC12423  SC22U6D3V5MX-2DLGP  [C805H54]  58.33 184.53 180 bottom
PC12424  SC22U6D3V5MX-2DLGP  [C805H54]  61.88 184.53 0 top
PC12425  SC22U6D3V5MX-2DLGP  [C805H54]  62.64 216.03 0 bottom
PC12426  SC22U6D3V5MX-2DLGP  [C805H54]  54.39 168.4 0 bottom
PC12427  SC22U6D3V5MX-2DLGP  [C805H54]  44.61 171.45 180 top
PC12428  SC22U6D3V5MX-2DLGP  [C805H54]  46.64 171.45 180 top
PC12429  SC22U6D3V5MX-2DLGP  [C805H54]  44.61 171.45 0 bottom
PC12430  SC22U6D3V5MX-2DLGP  [C805H54]  42.58 171.45 0 bottom
PC12431  SC22U6D3V5MX-2DLGP  [C805H54]  56.37 162.99 0 top
PC12432  SC22U6D3V5MX-2DLGP  [C805H54]  56.29 163.07 180 bottom
PC12433  SC22U6D3V5MX-2DLGP  [C805H54]  46.64 171.45 0 bottom
PC12434  SCD1U50V3KX-DL-GP  [C603H35]  159.67 165.86 90 top
PC12435  SCD1U50V3KX-DL-GP  [C603H35]  159.67 164.59 90 top
PC12436  SCD1U50V3KX-DL-GP  [C603H35]  159.67 161.42 90 top
PC12437  SCD1U50V3KX-DL-GP  [C603H35]  159.67 160.15 90 top
PC12438  SCD1U50V3KX-DL-GP  [C603H35]  158.02 150.62 0 top
PC12439  SC1U10V2KX-1DLGP  [C402H22]  37.5 139.57 0 bottom
PC12440  SC1U10V2KX-1DLGP  [C402H22]  160.18 167.51 0 top
PC12441  SC1U10V2KX-1DLGP  [C402H22]  158.15 169.93 180 top
PC12442  SC1U10V2KX-1DLGP  [C402H22]  160.31 172.85 270 top
PD4401  RB520SM-30T2R-GP  [D1608-035030AKH28]  38.01 48.77 270 bottom
PD4405  1N4148WS-7-F-GP  [SOD323AKH42]  35.47 48.77 90 top
PG3  GAP-CLOSE  [CON2C]  114.33 86.11 270 top
PG4  GAP-CLOSE  [CON2C]  120.18 86.11 90 top
PG4401  GAP-CLOSE-PWR-3-GP  [GAP-CLOSE-PWR-3]  62.26 42.16 180 top
PG4402  GAP-CLOSE-PWR-3-GP  [GAP-CLOSE-PWR-3]  62.26 43.94 180 top
PG4403  GAP-CLOSE-PWR-3-GP  [GAP-CLOSE-PWR-3]  38.79 66.67 180 top
PG4404  GAP-CLOSE-PWR-3-GP  [GAP-CLOSE-PWR-3]  38.79 64.9 180 top
PG4501  GAP-CLOSE-PWR-3-GP  [GAP-CLOSE-PWR-3]  132.37 10.29 180 bottom
PG4506  GAP-CLOSE-PWR-3-GP  [GAP-CLOSE-PWR-3]  149.56 17.73 270 top
PG4532  GAP-CLOSE-PWR-3-GP  [GAP-CLOSE-PWR-3]  145.58 5.08 0 top
PG4601  GAP-CLOSE-PWR-3-GP  [GAP-CLOSE-PWR-3]  20.23 208.79 0 top
PG4602  GAP-CLOSE-PWR-3-GP  [GAP-CLOSE-PWR-3]  21.37 190.88 270 top
PG4603  GAP-CLOSE-PWR-3-GP  [GAP-CLOSE-PWR-3]  20.35 190.88 270 top
PG4604  GAP-CLOSE-PWR-3-GP  [GAP-CLOSE-PWR-3]  23.02 209.68 90 top
PG4606  GAP-CLOSE-PWR-3-GP  [GAP-CLOSE-PWR-3]  30.89 191.64 270 top
PG4607  GAP-CLOSE-PWR-3-GP  [GAP-CLOSE-PWR-3]  31.91 191.64 270 top
PG4701  GAP-CLOSE-PWR-3-GP  [GAP-CLOSE-PWR-3]  40.17 180.21 180 top
PG4702  GAP-CLOSE-PWR-3-GP  [GAP-CLOSE-PWR-3]  44.23 180.21 0 top
PG4804  GAP-CLOSE-PWR-3-GP  [GAP-CLOSE-PWR-3]  54.64 210.95 180 top
PG4805  GAP-CLOSE-PWR-3-GP  [GAP-CLOSE-PWR-3]  58.71 210.95 0 top
PG4819  GAP-CLOSE-PWR-3-GP  [GAP-CLOSE-PWR-3]  54.64 199.77 180 top
PG4822  GAP-CLOSE-PWR-3-GP  [GAP-CLOSE-PWR-3]  58.71 199.77 0 top
PG5001  GAP-CLOSE-PWR-3-GP  [GAP-CLOSE-PWR-3]  39.91 164.08 180 top
PG5002  GAP-CLOSE-PWR-3-GP  [GAP-CLOSE-PWR-3]  42.96 164.08 0 top
PG5202  GAP-CLOSE-PWR-3-GP  [GAP-CLOSE-PWR-3]  51.21 154.05 90 top
PG5301  GAP-CLOSE-PWR-3-GP  [GAP-CLOSE-PWR-3]  107.35 77.98 90 top
PG5302  GAP-CLOSE-PWR-3-GP  [GAP-CLOSE-PWR-3]  103.92 72.95 270 top
PG8401  GAP-CLOSE-PWR-3-GP  [GAP-CLOSE-PWR-3]  102.52 101.09 270 top
PG8402  -  [0R0805-PAD]  116.49 107.95 270 top
PG8403  -  [0R0805-PAD]  102.78 104.01 270 top
PG8404  -  [0R0805-PAD]  116.49 105.92 270 top
PG8405  -  [0R0805-PAD]  102.78 106.05 270 top
PL1  IND-D36UH-19-GP  [L115100-2H158]  117.25 86.11 270 top
PL4301  MLVS0402M04-GP-U  [L402H24]  31.66 63.37 0 bottom
PL4302  MLVS0402M04-GP-U  [L402H24]  31.66 67.18 0 bottom
PL4303  MLVS0402M04-GP-U  [L402H24]  31.66 65.28 180 bottom
PL4401  IND-5D6UH-48-GP-U1  [L7066-1830-UH119]  40.67 59.31 180 top
PL4501  IND-2D2UH-122-GP-U  [L686647-127318H119]  142.78 16.26 0 top
PL4502  IND-2D2UH-122-GP-U  [L686647-127318H119]  132.75 16.26 180 top
PL4701  IND-D15UH-13-GP  [L112100-2030H158]  42.2 180.21 90 top
PL4801  IND-D15UH-13-GP  [L112100-2030H158]  56.68 210.95 90 top
PL4802  IND-D15UH-13-GP  [L112100-2030H158]  56.68 199.77 90 top
PL5001  IND-D47UH-33-GP-U  [L686647-127318H119]  41.44 164.08 90 top
PL5101  IND-1UH-93-GP  [L115100-2030H158]  97.82 214.25 0 top
PL5201  IND-1UH-93-GP  [L115100-2030H158]  43.85 151.76 90 top
PL5301  IND-1UH-94-GP-U  [L686647-127318H119]  112.43 76.07 270 top
PL8401  IND-1UH-210-GP  [L2520-D620H48]  106.59 104.78 270 top
PQ4204  PDTC124EU-1-GP  [SOT323CBE2D2H44]  91.6 34.04 180 top
PQ4205  PDTA124EU-1-GP  [SOT323CBE2D2H44]  89.57 28.45 180 top
PQ4206  2N7002K-2-GP  [SOT23DGS2D4H44]  89.7 39.5 180 top
PQ4401  2N7002KDW-GP  [SOT-363H44]  56.42 41.91 270 top
PQ4402  2N7002A-7-GP  [SOT23DGS2D4H48]  37.12 44.96 270 top
PQ4403  2N7002A-7-GP  [SOT23DGS2D4H48]  52.36 41.27 90 bottom
PQ4404  NTJD512NT1G-GP  [SOT-363H44]  56.42 41.91 90 bottom
PQ4405  2N7002K-2-GP  [SOT23DGS2D4H44]  52.36 44.83 90 bottom
PQ4406  2N7002A-7-GP  [SOT23DGS2D4H48]  52.36 42.29 90 top
PQ4409  MMBT3906-4-GP  [SOT23CBE2D4H44]  35.34 51.69 0 top
PQ5007  NTJD512NT1G-GP  [SOT-363H44]  72.55 68.07 0 bottom
PQ5008  2N7002KDW-GP  [SOT-363H44]  25.69 65.15 180 bottom
PR1  0R2J-2-GP  [R402H16]  131.61 108.08 270 top
PR2  -  [0R0402-PAD]  132.37 101.85 270 bottom
PR3  1KR2J-1-GP  [R402H16]  135.92 106.05 90 top
PR4  1KR2J-1-GP  [R402H16]  135.92 106.05 90 bottom
PR5  4K02R2F-GP  [R402H16]  129.32 102.74 0 bottom
PR6  1K91R2F-1-GP  [R402H16]  135.92 105.03 270 top
PR7  1KR2J-1-GP  [R402H16]  135.92 104.01 90 top
PR8  47KR2F-GP  [R402H16]  129.19 106.17 0 top
PR9  47KR2F-GP  [R402H16]  133.13 107.06 180 top
PR11  0R0402-PAD-2-GP  [0R0402-PAD-1]  123.22 106.17 90 top
PR12  0R2J-2-GP  [R402H16]  123.22 105.16 270 top
PR13  8K06R2F-GP  [R402H16]  131.61 107.06 270 top
PR15  1KR2J-1-GP  [R402H16]  135.92 105.03 90 bottom
PR16  1K21R2F-2-GP  [R402H16]  123.22 100.33 180 top
PR19  10KR2F-2-GP  [R402H16]  135.92 102.74 90 bottom
PR20  562R2F-GP  [R402H16]  127.16 106.17 180 top
PR21  1K87R2F-GP  [R402H16]  128.18 106.17 180 top
PR26  1KR2J-1-GP  [R402H16]  135.92 100.71 90 top
PR28  -  [0R0402-PAD]  123.86 104.01 90 top
PR29  -  [0R0402-PAD]  123.86 103 90 top
PR31  1KR2J-1-GP  [R402H16]  135.92 99.69 90 top
PR33  1KR2J-1-GP  [R402H16]  135.92 98.68 90 top
PR34  82D5R2F-1-GP  [R402H16]  124.24 100.33 180 top
PR40  1KR2J-1-GP  [R402H16]  135.92 95.63 90 top
PR42  2K61R2F-1-GP  [R402H16]  120.18 98.81 270 top
PR43  2D2R3-1-U-GP  [R603H22]  126.91 93.98 0 top
PR44  -  [0R0402-PAD]  131.22 92.99 90 top
PR45  3K65R3F-GP  [R603H22]  118.52 99.06 0 top
PR51  NTC-10K-27-GP-U  [NTC-402H24-U]  117.76 92.2 270 top
PR60  NTC-470K-9-GP-U  [NTC-402H24-U]  125.51 76.45 90 top
PR96  1KR2J-1-GP  [R402H16]  135.92 100.71 90 bottom
PR101  -  [0R0402-PAD]  121.32 95 90 top
PR102  1KR2J-1-GP  [R402H16]  135.92 97.66 90 bottom
PR103  1KR2J-1-GP  [R402H16]  135.92 96.65 90 bottom
PR1689  12K4R2F-GP  [R402H16]  95.16 124.21 0 top
PR4210  1KR2J-1-GP  [R402H16]  92.11 40.01 0 top
PR4214  3K3R6J-GP  [R1206H28]  88.93 33.78 180 top
PR4401  49K9R2F-L-GP  [R402H16]  60.49 40.64 180 top
PR4402  100KR2J-1-GP  [R402H16]  48.42 42.67 0 top
PR4403  20R5F-1GP  [R805H24]  46.9 50.16 90 bottom
PR4404  100KR2J-1-GP  [R402H16]  33.69 42.55 180 top
PR4405  102KR2F-GP  [R402H16]  43.98 40.77 180 bottom
PR4406  10R2F-L-GP  [R402H14]  36.99 45.72 90 bottom
PR4407  100KR2J-1-GP  [R402H16]  38.13 42.67 90 top
PR4408  110KR2F-GP  [R402H16]  46.52 43.43 180 top
PR4409  47KR2F-GP  [R402H16]  45.5 43.43 180 top
PR4410  -  [0R0402-PAD]  40.04 44.83 90 top
PR4411  56K2R2F-2-GP  [R402H16]  49.33 44.2 270 top
PR4412  0R5J-5-GP  [R805H24]  68.23 37.97 0 bottom
PR4413  100KR2J-1-GP  [R402H16]  61.5 40.64 0 top
PR4414  0R5J-5-GP  [R805H24]  66.2 38.61 0 bottom
PR4415  D01R3721F-GP-U  [R3720H40]  64.55 43.05 180 top
PR4416  33KR2F-GP  [R402H16]  40.04 43.81 90 top
PR4417  470KR2J-2-GP  [R402H16]  37.88 73.53 90 bottom
PR4418  0R5J-5-GP  [R805H24]  64.17 38.61 0 bottom
PR4419  0R5J-5-GP  [R805H24]  62.14 38.61 0 bottom
PR4420  3D3MR2J-GP  [R402H16]  48.42 44.58 180 bottom
PR4421  0R5J-5-GP  [R805H24]  70.77 37.97 180 top
PR4422  10KR2F-2-GP  [R402H16]  37.75 43.69 90 bottom
PR4423  7D5R2F-GP  [R402H16]  37.75 44.7 90 bottom
PR4424  309KR2F-GP  [R402H16]  46.26 41.15 270 top
PR4425  1D5R2F-GP  [R402H16]  40.8 48.84 90 bottom
PR4426  3K3R2J-3-GP  [R402H16]  42.2 40.89 180 top
PR4427  100KR2J-1-GP  [R402H16]  49.44 44.58 0 bottom
PR4428  107KR2F-GP  [R402H16]  49.33 45.21 90 top
PR4429  0R5J-5-GP  [R805H24]  68.74 37.97 180 top
PR4430  D01R3721F-GP-U  [R3720H40]  41.05 65.79 180 top
PR4431  -  [0R0402-PAD]  42.96 40.77 180 bottom
PR4432  3K3R2J-3-GP  [R402H16]  41.18 40.89 180 top
PR4433  10KR2F-2-GP  [R402H16]  54.8 45.06 180 bottom
PR4434  100KR2J-1-GP  [R402H16]  49.44 42.67 0 top
PR4435  2D2R5J-1-GP  [R805H24]  137.83 15.95 180 top
PR4450  10KR2F-2-GP  [R402H16]  26.96 69.09 180 bottom
PR4451  680KR2F-GP  [R402H16]  25.69 58.29 180 bottom
PR4455  0R2J-2-GP  [R402H16]  24.67 60.2 0 bottom
PR4458  0R2J-2-GP  [R402H16]  40.17 48.77 270 top
PR4462  0R2J-2-GP  [R402H16]  25.69 60.2 0 bottom
PR4501  2D2R2J-GP  [R402H16]  153.07 26.29 270 top
PR4502  -  [0R0805-PAD]  144.43 29.84 0 bottom
PR4503  10KR2F-2-GP  [R402H16]  157.77 24.64 180 top
PR4504  6K65R2F-GP  [R402H16]  156.75 24.64 0 top
PR4506  53K6R2F-GP  [R402H16]  154.08 21.72 180 bottom
PR4508  56KR2F-GP  [R402H16]  147.73 22.17 90 top
PR4509  100KR2J-1-GP  [R402H16]  155.1 27.3 270 top
PR4511  0R0402-PAD-2-GP  [0R0402-PAD-1]  147.73 23.19 90 top
PR4513  2D2R2J-GP  [R402H16]  153.2 17.78 270 top
PR4515  71K5R2F-1-GP  [R402H16]  157.21 23.14 90 top
PR4518  15KR2F-GP  [R402H16]  156.75 19.81 180 top
PR4519  10KR2F-2-GP  [R402H16]  157.77 19.81 0 top
PR4528  -  [0R0805-PAD]  148.5 29.84 0 bottom
PR4529  -  [0R0805-PAD]  146.46 29.84 0 bottom
PR4530  -  [0R0805-PAD]  129.83 26.04 0 bottom
PR4531  -  [0R0805-PAD]  127.8 26.04 0 bottom
PR4532  -  [0R0805-PAD]  125.76 26.04 0 bottom
